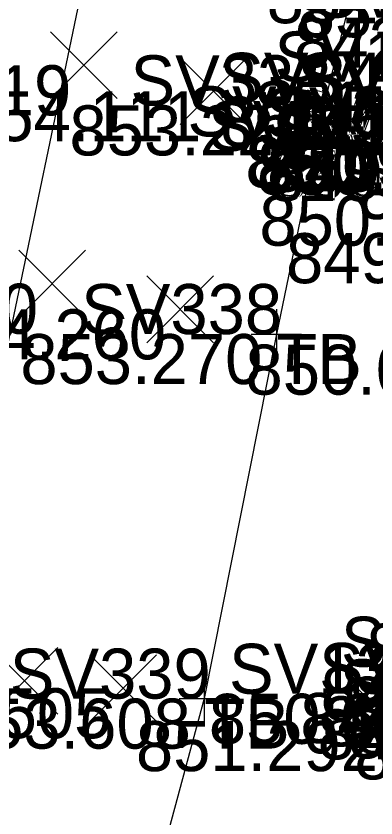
# Model space of a CAD drawing. Extents: x 2228183 to 2230895, y 679226 to 682223.
# Drawn here: x 2228324.74 to 2228331.93, y 680568.09 to 680584.12 of the extents above; entities that cross this region are included whole.
import ezdxf

# ---------------------------------------------------------------- set-up
doc = ezdxf.new("R2010")
doc.units = 0
for name, color, linetype in [('RD_X_GR_Rt', 7, 'Continuous'), ('SC_Scratch1', 7, 'Continuous'), ('SV_P_Control_Cells_Set', 7, 'Continuous'), ('SV_X_Random_Point', 7, 'Continuous'), ('SV_X_Shot_Marker', 7, 'Continuous'), ('SV_X_Text_Comment', 7, 'Continuous'), ('SV_X_Top_of_Bank', 7, 'Continuous')]:
    doc.layers.add(name, color=color, linetype=linetype)

msp = doc.modelspace()

# ---------------------------------------------------------------- linework, layer by layer
at = {"layer": 'RD_X_GR_Rt'}
msp.add_lwpolyline([(2228290.359, 680391.22), (2228294.274, 680415.932), (2228298.414, 680440.801), (2228302.718, 680465.177), (2228307.188, 680489.321), (2228312.206, 680513.859), (2228316.706, 680538.587), (2228321.519, 680562.878), (2228326.574, 680587.113), (2228331.32, 680611.864), (2228336.079, 680636.156), (2228341.093, 680660.882), (2228346.244, 680685.06), (2228350.849, 680709.572), (2228355.751, 680733.95), (2228357.804, 680743.718), (2228360.585, 680755.706), (2228364.08, 680768.892), (2228368.125, 680781.145)], dxfattribs=at)
at = {"layer": 'SV_X_Random_Point'}
for p, q in [((2228325.43, 680582.472), (2228326.764, 680583.807)), ((2228325.43, 680583.807), (2228326.764, 680582.472)), ((2228328.023, 680581.954), (2228329.357, 680583.289)), ((2228328.023, 680583.289), (2228329.357, 680581.954)), ((2228324.797, 680578.105), (2228326.131, 680579.44)), ((2228324.797, 680579.44), (2228326.131, 680578.105)), ((2228327.354, 680577.593), (2228328.688, 680578.928)), ((2228327.354, 680578.928), (2228328.688, 680577.593)), ((2228324.242, 680570.166), (2228325.576, 680571.501)), ((2228324.242, 680571.501), (2228325.576, 680570.166)), ((2228326.217, 680570.019), (2228327.551, 680571.354)), ((2228326.217, 680571.354), (2228327.551, 680570.019)), ((2228331.545, 680569.363), (2228332.879, 680570.698)), ((2228331.545, 680570.698), (2228332.879, 680569.363))]:
    msp.add_line(p, q, dxfattribs=at)
at = {"layer": 'SV_X_Shot_Marker'}
for p, q in [((2228330.895, 680582.837), (2228330.895, 680581.837)), ((2228330.395, 680582.337), (2228331.395, 680582.337)), ((2228330.895, 680582.337), (2228330.895, 680582.337)), ((2228329.944, 680578.266), (2228329.944, 680577.266)), ((2228329.444, 680577.766), (2228330.444, 680577.766)), ((2228329.944, 680577.766), (2228329.944, 680577.766)), ((2228328.503, 680570.979), (2228328.503, 680569.979)), ((2228328.003, 680570.479), (2228329.003, 680570.479)), ((2228328.503, 680570.479), (2228328.503, 680570.479))]:
    msp.add_line(p, q, dxfattribs=at)
at = {"layer": 'SV_X_Top_of_Bank'}
msp.add_lwpolyline([(2228351.296, 680683.864), (2228348.585, 680671.422), (2228345.681, 680659.56), (2228343.564, 680646.922), (2228341.433, 680634.625), (2228339.657, 680626.067), (2228337.837, 680616.265), (2228336.717, 680610.616), (2228334.631, 680604.814), (2228334.097, 680599.023), (2228332.268, 680590.812), (2228331.694, 680589.223), (2228331.741, 680585.744), (2228330.895, 680582.337), (2228329.944, 680577.766), (2228328.503, 680570.479), (2228326.177, 680561.862), (2228324.56, 680553.967), (2228324.09, 680547.312), (2228322.098, 680537.165), (2228319.616, 680531.838), (2228317.404, 680525.616)], dxfattribs=at)

# ---------------------------------------------------------------- texts
at = {"layer": 'SC_Scratch1'}
for s, p in [('851.330', (2228329.751, 680583.98)), ('851.006', (2228330.372, 680583.7)), ('842.888', (2228330.297, 680583.091)), ('854.719', (2228321.013, 680582.139)), ('851.311', (2228329.506, 680581.813)), ('854.111', (2228323.608, 680581.621)), ('851.575', (2228328.823, 680581.515)), ('849.884', (2228329.922, 680581.372)), ('842.998', (2228329.967, 680581.388)), ('842.998', (2228329.967, 680581.388)), ('853.229', (2228325.811, 680581.337)), ('850.922', (2228329.358, 680580.717)), ('850.922', (2228329.325, 680580.695)), ('850.619', (2228329.549, 680580.552)), ('850.647', (2228329.561, 680580.644)), ('849.964', (2228329.758, 680580.611)), ('850.980', (2228329.791, 680580.631)), ('849.899', (2228329.76, 680580.426)), ('849.899', (2228329.787, 680580.436)), ('850.006', (2228329.829, 680580.465)), ('848.769', (2228331.581, 680580.064)), ('848.769', (2228331.583, 680580.077)), ('850.449', (2228329.605, 680579.533)), ('849.828', (2228330.138, 680578.783)), ('854.940', (2228320.35, 680577.772)), ('854.260', (2228322.907, 680577.26)), ('853.270', (2228324.83, 680576.766)), ('850.071', (2228329.329, 680576.555)), ('848.351', (2228331.748, 680570.979)), ('848.802', (2228330.83, 680570.116)), ('848.184', (2228331.394, 680569.917)), ('854.505', (2228321.814, 680569.686)), ('850.612', (2228328.596, 680569.575)), ('848.977', (2228330.422, 680569.592)), ('848.548', (2228330.866, 680569.525)), ('853.608', (2228323.403, 680569.479)), ('848.726', (2228330.768, 680569.265)), ('848.189', (2228331.38, 680569.285)), ('851.292', (2228327.139, 680569.03)), ('848.405', (2228331.503, 680568.864))]:
    msp.add_text(s, height=1, dxfattribs=at).set_placement(p)
at = {"layer": 'SV_P_Control_Cells_Set'}
for s, p in [('SV3434', (2228330.677, 680584.091)), ('SV1439', (2228329.906, 680582.813)), ('SV333', (2228327.031, 680582.337)), ('SV3433_1', (2228328.804, 680582.388)), ('SV1419', (2228330.362, 680582.372)), ('SV3433', (2228330.405, 680582.388)), ('SV1437_1', (2228328.168, 680581.717)), ('SV1437', (2228329.704, 680581.695)), ('SV1436', (2228329.955, 680581.644)), ('SV1438', (2228330.206, 680581.631)), ('SV1435', (2228330.212, 680581.611)), ('SV1418_1', (2228328.58, 680581.426)), ('SV1418', (2228330.172, 680581.436)), ('SV1417_1', (2228330.401, 680581.064)), ('SV338', (2228326.044, 680577.766)), ('SV1365', (2228331.234, 680571.116)), ('SV339', (2228324.619, 680570.479)), ('SV1352', (2228328.998, 680570.575)), ('SV1364', (2228330.798, 680570.592)), ('SV1363', (2228331.21, 680570.265))]:
    msp.add_text(s, height=1, dxfattribs=at).set_placement(p)
at = {"layer": 'SV_X_Text_Comment'}
for p in [(2228330.895, 680581.337), (2228329.944, 680576.766), (2228328.503, 680569.479)]:
    msp.add_text('TB', height=1, dxfattribs=at).set_placement(p)

doc.saveas('drawing.dxf')
